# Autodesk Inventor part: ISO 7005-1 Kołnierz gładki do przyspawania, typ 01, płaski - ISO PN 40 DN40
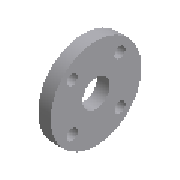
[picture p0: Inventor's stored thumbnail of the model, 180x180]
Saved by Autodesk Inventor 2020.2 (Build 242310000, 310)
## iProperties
NAME: PIPING: ISO 7005-1 Plate Flange for Welding Type 01 Flat Face - PN 40
DATA: <meta><inlinegroups number="1" deflen="1.6"></inlinegroups><connections number="2"></connections><angles><a>3.14159265358979</a></angles></meta>
Manager: www.cadconsulting.pl
Company: Fabian Stasiak CAD Consulting
Created: 2014-02
Part Number: ISO 7005-1 Kołnierz gładki do przyspawania, typ 01, płaski - ISO PN 40 DN40
Material: Stal
Description: Kołnierze metalowe - Część 1: Kołnierze stalowe - Kołnierz gładki do przyspawania, typ 01, płaski - ISO PN 40
Document SubType Name: Modeling
Standard: ISO 7005-1
Designer: F.Stasiak
Standard Revision: First edition 1992-04-15
Standards Organization: ISO
Language: pl-PL
Size Designation: DN40
Categories: <MemberInstance><Categories><Category DisplayName="Rury cienko- i grubościenne" InternalName="4347fa0f-2144-441d-94cd-e3e15c92b736" Mnemonic="TUBEANDPIPE"><Cate
Density: 1 g/cm^3
Appearance: Płyta
Catalog Web Link: www.expertbooks.pl
IsCustomPart: 0
Author: F.Stasiak
Subject: Zbiór ćwiczeń. Autodesk Inventor 2020. Kurs Professional
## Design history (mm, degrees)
sketch "Sketch1"
  geometry: L1 (18, 75)-(0, 75); L2 (0, 75)-(0, 24.75); L3 (0, 24.75)-(0, 0) reference; L4 (0, 0)-(18, 0) reference; L5 (18, 75)-(18, 24.75); L6 (18, 24.75)-(0, 24.75); L7 (18, 24.75)-(18, 0)
  constraints: 14 end point, 2 parallel, 2 perpendicular, 1 collinear, 1 horizontal, 1 vertical
  dimensions: "d0" = 150 diameter of L1 L4 (= D); "d1" = 18 distance of L1.start L1.end (= C1); "d6" = 49.5 diameter of L6 L4 (= B1)
revolve "Revolution1" stored, may be unused: angle "d11" = 90 deg
sketch "Sketch2"
  geometry: L1 (0, 55)-(0, 0); L2 (0, 0)-(38.891, 38.891); C1 r 24.75 at (0, 0) reference; C2 r 75 at (0, 0) reference; C3 r 9 at (38.891, 38.891); A1 r 55 centre (0, 0) between (0, 55) and (38.891, 38.891)
  constraints: 4 end point, 2 centre point, 2 point on circle, 1 coincident, 1 concentric, 1 vertical
  dimensions: "d2" = 110 diameter of A1 (= K1); "d7" = 18 diameter of C3 (= L); "d8" = 45 deg angle of L1 L2 (computed from NU)
extrude "Extrusion1" cut sketch "Sketch2" extent not by distance; taper "d3" = 0 deg; stored distance "d19" = 25.4
pattern_circular "Circular Pattern1" dims angle "d5" = 360 deg
workaxis "Work Axis1"
workpoint "Work Point1"
workpoint "Work Point2"
workaxis "Work Axis2"
workpoint "Work Point3"
body "Solid1"
other parameters: "C1" = 18 [user parameter; used in 1 equation term], "D" = 150 [user parameter; used in 1 equation term], "K1" = 110 [user parameter; used in 1 equation term], "L" = 18 [user parameter; used in 1 equation term], "B1" = 49.5 [user parameter; used in 1 equation term], "NB" = 12.345 [user parameter], "Size_Designation" = 12.345 [user parameter]
